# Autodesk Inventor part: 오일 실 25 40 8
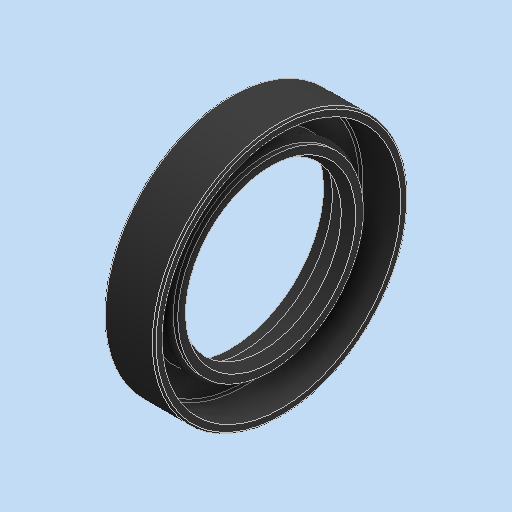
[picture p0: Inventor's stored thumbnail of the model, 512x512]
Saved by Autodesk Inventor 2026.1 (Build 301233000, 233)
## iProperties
Created: 2025-11
Part Number: 오일 실 25 40 8
Material: 고무
Description: 오일-실
Document SubType Name: Modeling
Designer: PC-30
Density: 0.93 g/cm^3
Appearance: 기본값
Author: jhkim
Sending System: Autodesk Inventor 2026
Preprocessor: ST-DEVELOPER v20.1
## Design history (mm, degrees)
feature "Solid1"
node "솔리드1"
